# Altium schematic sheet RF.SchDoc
size A3
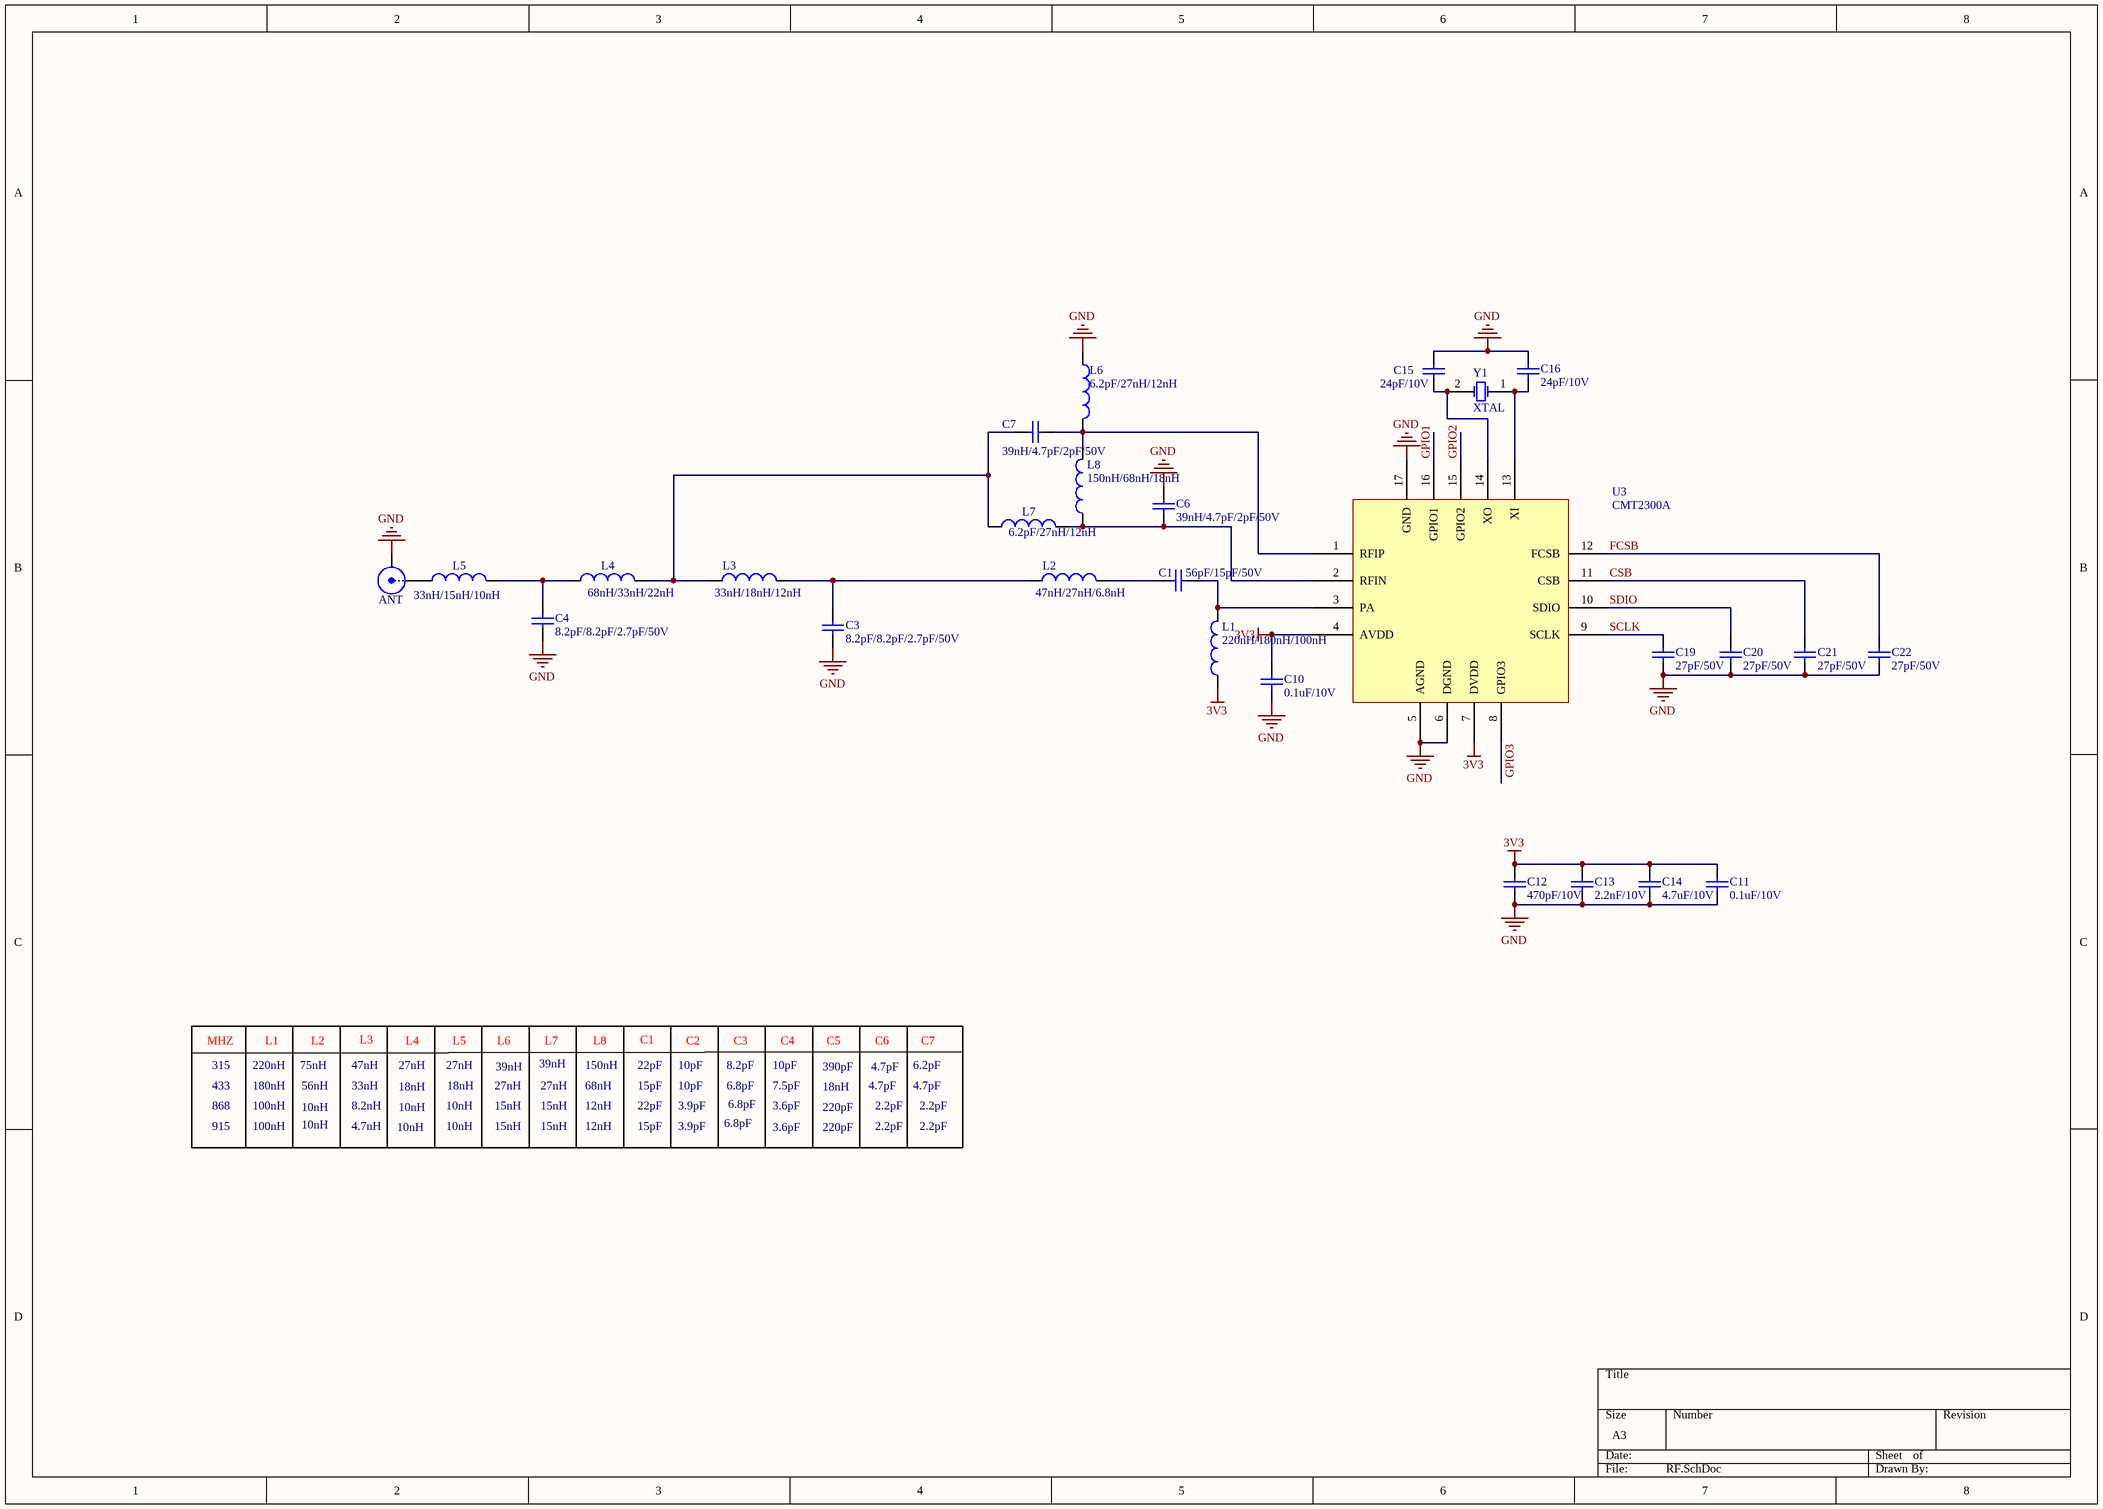
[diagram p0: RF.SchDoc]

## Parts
ANT  (no value)  [SMA Straight SMD]
C1  56pF/15pF/50V  [0603C]
C3  8.2pF/8.2pF/2.7pF/50V  [0603C]
C4  8.2pF/8.2pF/2.7pF/50V  [0603C]
C6  39nH/4.7pF/2pF/50V  [0603C]
C7  39nH/4.7pF/2pF/50V  [0603C]
C10  0.1uF/10V  [0603C]
C11  0.1uF/10V  [0603C]
C12  470pF/10V  [0603C]
C13  2.2nF/10V  [0603C]
C14  4.7uF/10V  [0603C]
C15  24pF/10V  [0603C]
C16  24pF/10V  [0603C]
C19  27pF/50V  [0603C]
C20  27pF/50V  [0603C]
C21  27pF/50V  [0603C]
C22  27pF/50V  [0603C]
L1  220nH/180nH/100nH  [0603R]
L2  47nH/27nH/6.8nH  [0603R]
L3  33nH/18nH/12nH  [0603R]
L4  68nH/33nH/22nH  [0603R]
L5  33nH/15nH/10nH  [0603R]
L6  6.2pF/27nH/12nH  [0603R]
L7  6.2pF/27nH/12nH  [0603R]
L8  150nH/68nH/18nH  [0603R]
U3  CMT2300A
Y1  XTAL  [BCY-W2/D3.1]

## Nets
3V3: C10.1 C11.1 C12.1 C13.1 C14.1 L1.1 U3.4(AVDD) U3.7(DVDD)
GND: ANT.2(GND) C3.2 C4.2 C6.2 C10.2 C11.2 C12.2 C13.2 C14.2 C15.1 C16.1 C19.2 C20.2 C21.2 C22.2 L6.1 U3.5(AGND) U3.6(DGND) U3.17(GND)
CSB: C21.1 U3.11(CSB)
FCSB: C22.1 U3.12(FCSB)
GPIO1: U3.16(GPIO1)
GPIO2: U3.15(GPIO2)
GPIO3: U3.8(GPIO3)
SCLK: C19.1 U3.9(SCLK)
SDIO: C20.1 U3.10(SDIO)
NetANT_1: ANT.1(Signal) L5.1
NetC1_1: C1.1 L2.2
NetC1_2: C1.2 L1.2 U3.3(PA)
NetC3_1: C3.1 L2.1 L3.2
NetC4_1: C4.1 L4.1 L5.2
NetC6_1: C6.1 L7.2 L8.1 U3.2(RFIN)
NetC7_1: C7.1 L3.1 L4.2 L7.1
NetC7_2: C7.2 L6.2 L8.2 U3.1(RFIP)
NetC15_2: C15.2 U3.14(XO) Y1.2(OSC2)
NetC16_2: C16.2 U3.13(XI) Y1.1(OSC1)

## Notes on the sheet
- MHZ
- L1
- L2
- L3
- L4
- L5
- L6
- L7
- L8
- C1
- C2
- C3
- C4
- C5
- C6
- C7
- 315
- 433
- 868
- 220nH
- 180nH
- 100nH
- 75nH
- 56nH
- 10nH
- 47nH
- 33nH
- 8.2nH
- 27nH
- 18nH
- 15nH
- 39nH
- 150nH
- 68nH
- 12nH
- 22pF
- 15pF
- 10pF
- 3.9pF
- 6.8pF
- 8.2pF
- 7.5pF
- 3.6pF
- 390pF
- 220pF
- 4.7pF
- 2.2pF
- 6.2pF
- 915
- 4.7nH

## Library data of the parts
ANT = SMA: SMA Straight Connector
C1 C3 C4 C6 C7 C10-C16 C19-C22 = Cap: Capacitor; Value: 106
L1-L8 = Inductor: Code_IEC: 1005; Value: 10mH
Y1 = XTAL: Crystal Oscillator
